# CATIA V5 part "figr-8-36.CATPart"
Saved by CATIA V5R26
Part number: Part1
Bounding box of the stored display mesh (mm): x -75 to 75, y -75 to 75, z 0 to 20
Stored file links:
  D:\_Deepak\CATIA\CATIA V5-6R2016_Deepak\Resources\Part files\Partfiles\c08_catia_v5_6r2016_prt\figr-8-36.CATPart
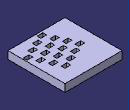
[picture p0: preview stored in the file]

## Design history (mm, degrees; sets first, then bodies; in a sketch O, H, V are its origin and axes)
Body1 (main body)
  Sketch1 on xy-plane, origin (0, 0, 0), H (1, 0, 0), V (0, 1, 0)
    line L1 (-75, 75) -> (75, 75)
    line L2 (75, 75) -> (75, -75)
    line L3 (75, -75) -> (-75, -75)
    line L4 (-75, -75) -> (-75, 75)
    axis line L5 (75, -75) -> (-75, 75)
    length L3 = 150
    length L2 = 150
    horizontal: L1 H, L3 H
    vertical: L2 V, L4 V
    midpoint: O L5
  Pad1: profile Sketch1, direction (0, 0, 1), length 20
  Sketch2 on face of Pad1, origin (0, 0, 20), H (1, 0, 0), V (0, 1, 0)
    line L1 (25, 40) -> (40, 40)
    line L2 (40, 40) -> (40, 30)
    line L3 (40, 30) -> (25, 30)
    line L4 (25, 30) -> (25, 40)
    reference projected line E1 (75, -75) -> (75, 75) from edge [face of Pad1 | face of Pad1]
    reference projected line E2 (75, 75) -> (-75, 75) from edge [face of Pad1 | face of Pad1]
    length L3 = 15
    length L4 = 10
    distance L2 E1 = 35
    distance L1 E2 = 35
    horizontal: L1 H, L3 H
    vertical: L2 V, L4 V
  Pocket1: profile Sketch2, direction (0, 0, -1), through (limit type 3)
  RectPattern1: of Pocket1, direction 1 instances 4, spacing 25, along edge [face of Pad1 | face of Pad1] reversed, direction 2 instances 4, spacing 25, along edge [face of Pad1 | face of Pad1], rotation -25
